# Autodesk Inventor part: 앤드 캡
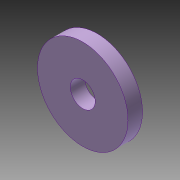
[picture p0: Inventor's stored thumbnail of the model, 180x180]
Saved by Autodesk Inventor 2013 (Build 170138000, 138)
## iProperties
Created: 2024-02
Part Number: 앤드 캡
Material: 강철, 연강
Document SubType Name: Modeling
Designer: mdu-01
Density: 1 g/cm^3
Author: mdu-01
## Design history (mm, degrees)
sketch "스케치1" dims "d0" = 18.29645 (derived)
  geometry: L1 (19.05, 2.5)-(19.05, -2.5) reference; C1 r 10 at (10.25, 0); C2 r 2.75 at (10.25, 0); A1 r 6.5 centre (10.25, 0) between (16.25, 2.5) and (16.25, -2.5) reference; 2 further points
  constraints: 3 coincident, 2 centre point, 3 other
  dimensions: "d1" = 20 diameter of C1; "d2" = 5.5 diameter of C2
extrude "돌출1" new body sketch "스케치1" distance "d3" = 3.2; taper "d4" = 0 deg
node "솔리드1"
node "참조1"
node "참조2"
